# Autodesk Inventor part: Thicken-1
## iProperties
Shininess: 64.0
Length Units: 11269
Angle Units: 11279
Time Units: 11290
Mass Units: 11283
Length Display Precision: 3
Angle Display Precision: 2
Compacted: True
Part Number: Thicken-1
Document SubType Name: Modeling
Created: 2002-12
Designer: deepak
Density: 0.0
Volumn: 0.0
Area: 0.0
PropertySet Name: Model Information
Control State: 0
Master: False
Checked Out: False
Author: deepak
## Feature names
1. Extrusion1
2. Fillet1
